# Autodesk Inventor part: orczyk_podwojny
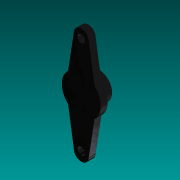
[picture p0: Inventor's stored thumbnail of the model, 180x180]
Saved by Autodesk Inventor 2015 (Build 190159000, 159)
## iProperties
Created: 2016-02
Part Number: orczyk_podwojny
Material: Generic
Document SubType Name: Modeling
Designer: Rafał
Density: 1 g/cm^3
Appearance: Glossy - Black
Author: Rafał
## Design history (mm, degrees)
sketch "Sketch1" dims "d3" = 32.5
  geometry: L1 (0, 0)-(0, -19.25); L2 (0, -19.25)-(0, -16.75); L3 (2.5, -16.75)-(0, -16.75); L4 (2.5, -16.75)-(4.413, -4.773); L5 (-2.5, -16.75)-(-4.413, -4.773); L6 (6.5, 0)-(-6.5, 0); L7 (2.5, 16.75)-(4.413, 4.773); L8 (-2.5, 16.75)-(-4.413, 4.773); C1 r 1.25 at (0, -16.25); C2 r 1.25 at (0, 16.25); A1 r 2.5 centre (0, -16.75) between (-2.5, -16.75) and (2.5, -16.75); A2 r 2.5 centre (0, 16.75) between (2.5, 16.75) and (-2.5, 16.75); A3 r 6.5 centre (0, 0) between (4.413, -4.773) and (4.413, 4.773); A4 r 6.5 centre (0, 0) between (-4.413, 4.773) and (-4.413, -4.773); 2 further points
  constraints: 16 end point, 11 point on circle, 6 centre point, 6 symmetric about line, 3 coincident, 2 horizontal, 2 point on line, 1 vertical, 1 vertical alignment, 4 other
  dimensions: "d1" = 19.25 distance of L1.start L1.end; "d2" = 2.5 distance of L2.end L1.end; "d4" = 2.5 diameter of C1
extrude "Extrusion1" new body sketch "Sketch1" distance "d5" = 2.3; taper "d6" = 0 deg
sketch "Sketch2"
  geometry: C1 r 4.5 at (0, 0); 1 further point
  constraints: 1 centre point, 1 coincident
  dimensions: "d7" = 9 diameter of C1
extrude "Extrusion2" join sketch "Sketch2" distance "d8" = 3.5; taper "d9" = 0 deg
sketch "Sketch3"
  geometry: C1 r 3 at (0, 0); 1 further point
  constraints: 1 centre point, 1 coincident
  dimensions: "d10" = 6 diameter of C1
extrude "Extrusion3" cut sketch "Sketch3" distance "d11" = 3.5; taper "d12" = 0 deg
body "Solid1"
other parameters: "d0" = 13
